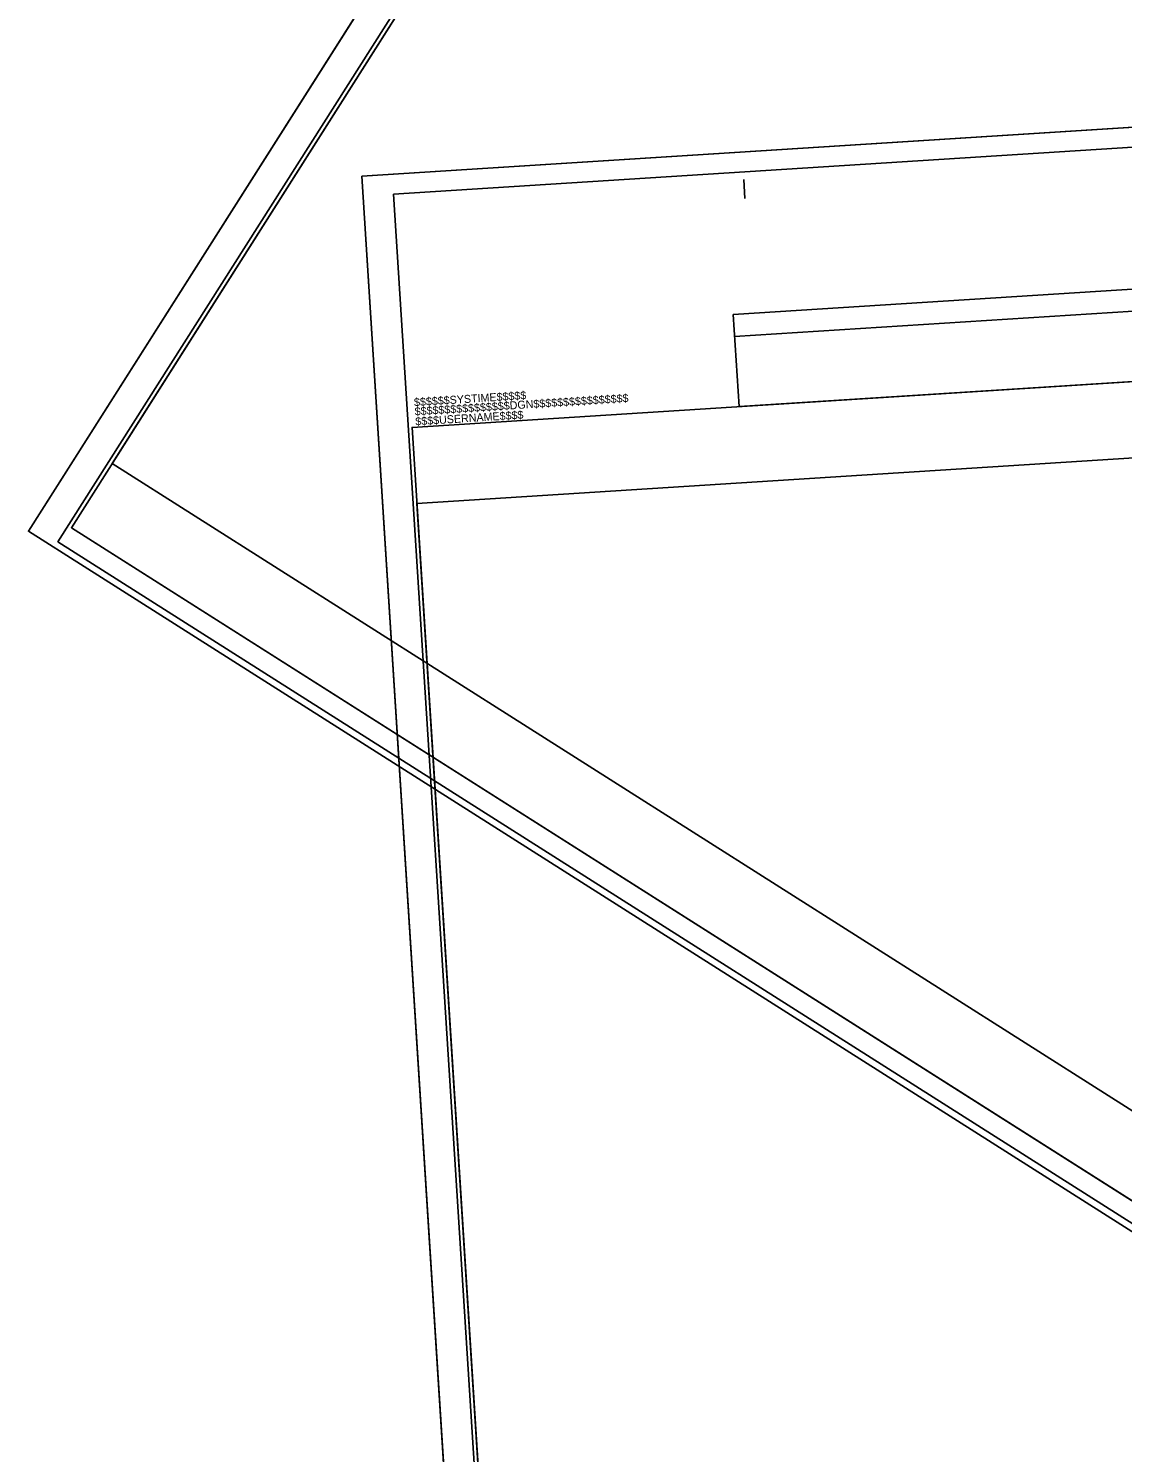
# Model space of a CAD drawing. Extents: x 1778994 to 1784559, y 810461 to 816654.
# Drawn here: x 1780200 to 1780917, y 811304 to 812239 of the extents above; entities that cross this region are included whole.
import ezdxf

# ---------------------------------------------------------------- set-up
doc = ezdxf.new("R2010")
doc.units = 0
for name, color, linetype in [('Sheet Block Revision CELL', 7, 'Continuous'), ('Sheet Clip Boundary CELL', 7, 'Continuous'), ('Sheet Cutting Line CELL', 7, 'Continuous'), ('Sheet Detail CELL', 7, 'Continuous'), ('Sheet Layout Plan Border', 7, 'Continuous'), ('Sheet Plan CELL', 7, 'Continuous'), ('Sheet Plan Layout CELL', 7, 'Continuous'), ('Sheet Plot Border Inside CELL', 7, 'Continuous'), ('Sheet Plot Border Outside CELL', 7, 'Continuous')]:
    doc.layers.add(name, color=color, linetype=linetype)

msp = doc.modelspace()

# ---------------------------------------------------------------- linework, layer by layer
at = {"layer": 'Sheet Block Revision CELL'}
msp.add_line((1780662.92, 812036.32), (1781451.96, 812086.48), dxfattribs=at)
msp.add_lwpolyline([(1780661.97, 812050.84), (1781451.03, 812100.99), (1781454.89, 812040.57), (1780665.83, 811990.43)], close=True, dxfattribs=at)
at = {"layer": 'Sheet Clip Boundary CELL'}
for points in [[(1781004.66, 813135.18), (1780254.51, 811953.1), (1780962.49, 811503.81), (1781063.9, 811663.61), (1781242.47, 811550.29), (1781891.21, 812572.57)], [(1780454.44, 811926.9), (1780543.23, 810529.71), (1781380.05, 810582.89), (1781368.05, 810771.77), (1781579.11, 810785.19), (1781502.32, 811993.5)]]:
    msp.add_lwpolyline(points, close=True, dxfattribs=at)
at = {"layer": 'Sheet Cutting Line CELL'}
for p, q in [((1781101.65, 813330.03), (1780199.6, 811908.59)), ((1781511.04, 812210.98), (1780418.24, 812141.53)), ((1780418.24, 812141.53), (1780525.01, 810461.42))]:
    msp.add_line(p, q, dxfattribs=at)
at = {"layer": 'Sheet Layout Plan Border'}
for points in [[(1781004.66, 813135.18), (1780254.51, 811953.1), (1780962.49, 811503.81), (1781063.9, 811663.61), (1781242.47, 811550.29), (1781891.21, 812572.57)], [(1780454.44, 811926.9), (1780543.23, 810529.71), (1781380.05, 810582.89), (1781368.05, 810771.77), (1781579.11, 810785.19), (1781502.32, 811993.5)]]:
    msp.add_lwpolyline(points, close=True, dxfattribs=at)
at = {"layer": 'Sheet Plan CELL'}
for p, q in [((1780668.88, 812139.41), (1780669.66, 812126.93)), ((1780451.27, 811976.8), (1780451.27, 811976.8))]:
    msp.add_line(p, q, dxfattribs=at)
for points in [[(1781114.25, 811348.25), (1781918, 812614.78), (1781031.45, 813177.39), (1780227.72, 811910.89)], [(1781031.45, 813177.39), (1781917.99, 812614.82), (1781221.47, 811517.18), (1781094.76, 811597.57), (1780987.56, 811428.68), (1780227.72, 811910.89)], [(1780451.27, 811976.8), (1781499.13, 812043.42), (1781581.61, 810746.05), (1781431.85, 810736.52), (1781444.53, 810536.89), (1780546.4, 810479.81)], [(1781594.29, 810546.38), (1781499.15, 812043.4), (1780451.27, 811976.8), (1780546.4, 810479.81)]]:
    msp.add_lwpolyline(points, close=True, dxfattribs=at)
at = {"layer": 'Sheet Plan Layout CELL'}
for points in [[(1781917.99, 812614.82), (1781031.45, 813177.39), (1780227.72, 811910.9), (1780935.71, 811461.6), (1781063.9, 811663.61), (1781242.47, 811550.29)], [(1781499.13, 812043.42), (1780451.27, 811976.8), (1780546.4, 810479.82), (1781383.23, 810533), (1781368.05, 810771.77), (1781579.11, 810785.19)]]:
    msp.add_lwpolyline(points, close=True, dxfattribs=at)
at = {"layer": 'Sheet Plot Border Inside CELL'}
for points in [[(1781111.57, 813308.33), (1780218.91, 811901.68), (1781109.67, 811336.39), (1782002.34, 812743.04)], [(1780439.02, 812129.82), (1780544.7, 810467.19), (1781597.56, 810534.09), (1781491.9, 812196.73)]]:
    msp.add_lwpolyline(points, close=True, dxfattribs=at)
at = {"layer": 'Sheet Plot Border Outside CELL'}
for points in [[(1781101.65, 813330.03), (1780199.6, 811908.59), (1781124.14, 811321.87), (1782026.2, 812743.3)], [(1780418.24, 812141.53), (1780525.01, 810461.42), (1781617.81, 810530.87), (1781511.04, 812210.98)]]:
    msp.add_lwpolyline(points, close=True, dxfattribs=at)

# ---------------------------------------------------------------- texts
at = {"layer": 'Sheet Detail CELL'}
msp.add_text('TO PLOT 34"(HALF SIZE)', height=75, rotation=321.63093, dxfattribs=at).set_placement((1780445.73, 812696.88))
at = {"layer": 'Sheet Plan CELL'}
for s, p in [('$$$$$$SYSTIME$$$$$', (1780452.73, 811990.64)), ('$$$$$$$$$$$$$$$$DGN$$$$$$$$$$$$$$$$', (1780453.14, 811984.58)), ('$$$$USERNAME$$$$', (1780453.57, 811978.04))]:
    msp.add_text(s, height=5.25, rotation=3.63631, dxfattribs=at).set_placement(p)

doc.saveas('drawing.dxf')
